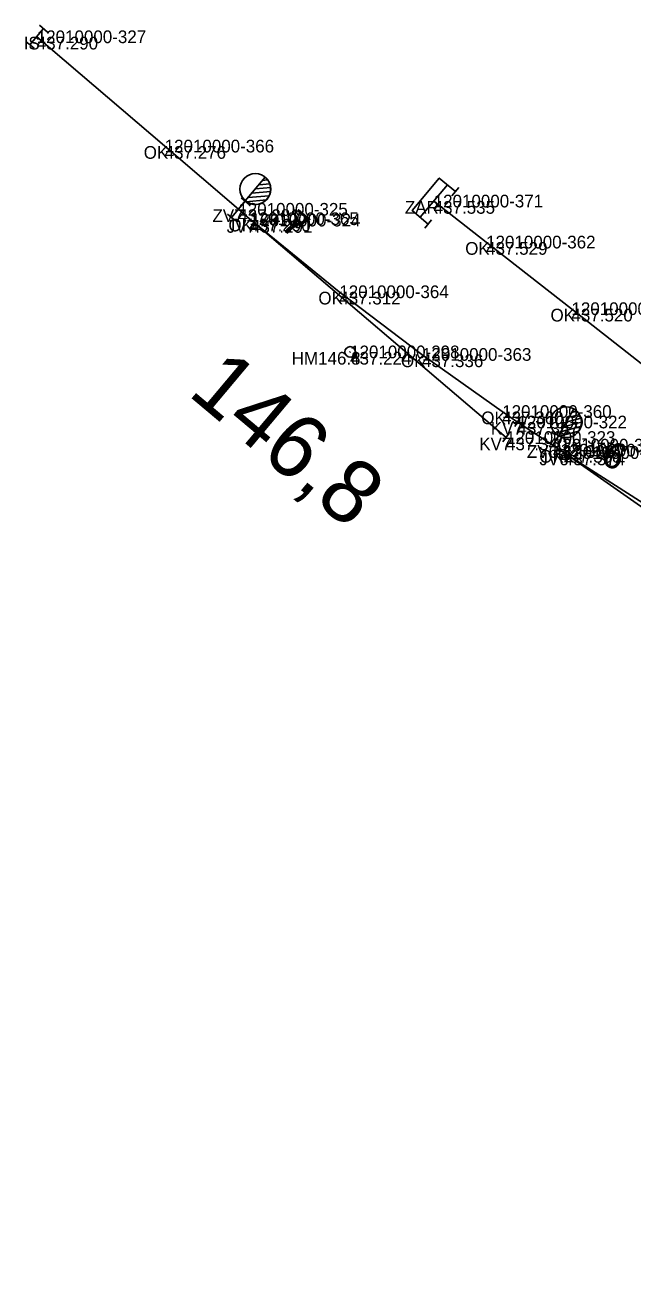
# Model space of a CAD drawing. Extents: x -653665 to -652742, y -1166300 to -1165487.
# Drawn here: x -653457.5 to -653400, y -1165780.3 to -1165660.7 of the extents above; entities that cross this region are included whole.
import ezdxf

# ---------------------------------------------------------------- set-up
doc = ezdxf.new("R2010")
doc.units = 0
for name, color, linetype in [('Vrstva 1', 7, 'Continuous'), ('Vrstva 15', 7, 'Continuous'), ('Vrstva 2', 7, 'Continuous'), ('Vrstva 3', 7, 'Continuous'), ('Vrstva 60', 7, 'Continuous'), ('Vrstva 61', 7, 'Continuous'), ('Vrstva 62', 7, 'Continuous'), ('Vrstva 7', 7, 'Continuous')]:
    doc.layers.add(name, color=color, linetype=linetype)

msp = doc.modelspace()

# ---------------------------------------------------------------- linework, layer by layer
at = {"layer": 'Vrstva 1'}
for points in [[(-653437.34, -1165678.06), (-653444.31, -1165672.07), (-653456.41, -1165661.74)], [(-653407.58, -1165700.37), (-653410.93, -1165698.18), (-653412.38, -1165697.19), (-653419.97, -1165691.79), (-653427.79, -1165685.86), (-653436.14, -1165679.08), (-653436.3, -1165678.95), (-653437.34, -1165678.06)], [(-653412.02, -1165699.65), (-653436.14, -1165679.08), (-653436.3, -1165678.95), (-653437.34, -1165678.06)], [(-653322.72, -1165752.72), (-653325.73, -1165750.35), (-653329.43, -1165747.45), (-653337.98, -1165740.73), (-653346.02, -1165734.53), (-653350.36, -1165731.09), (-653358.44, -1165724.74), (-653366.11, -1165718.7), (-653373.96, -1165712.53), (-653382.2, -1165706.04), (-653390.04, -1165699.88), (-653398.07, -1165693.55), (-653405.83, -1165687.47), (-653413.9, -1165681.16), (-653418.86, -1165677.28)], [(-653303.11, -1165780.26), (-653310.99, -1165774.05), (-653319.17, -1165767.61), (-653327.03, -1165761.43), (-653331.89, -1165757.62), (-653335.5, -1165754.8), (-653344.08, -1165748.08), (-653352.04, -1165741.96), (-653356.22, -1165738.72), (-653363.93, -1165732.78), (-653371.45, -1165727), (-653371.62, -1165726.86), (-653379.2, -1165721.04), (-653387.07, -1165715.03), (-653387.21, -1165714.92), (-653393.27, -1165710.42), (-653395.2, -1165709.02), (-653406.55, -1165701.06), (-653406.89, -1165700.83), (-653407.58, -1165700.37)], [(-653381.84, -1165716.08), (-653384.56, -1165714.53), (-653386.13, -1165713.64), (-653386.38, -1165713.51), (-653392.82, -1165709.75), (-653395.64, -1165708.03), (-653406.55, -1165701.06), (-653406.89, -1165700.83), (-653407.58, -1165700.37)]]:
    msp.add_lwpolyline(points, dxfattribs=at)
at = {"layer": 'Vrstva 15'}
for p, q in [((-653420.15, -1165678.81), (-653417.57, -1165675.75)), ((-653417.13, -1165676.78), (-653416.49, -1165676.01)), ((-653419.7, -1165679.84), (-653419.06, -1165679.07))]:
    msp.add_line(p, q, dxfattribs=at)
msp.add_lwpolyline([(-653416.81, -1165676.39), (-653418.34, -1165675.11), (-653420.91, -1165678.17), (-653419.38, -1165679.46)], dxfattribs=at)
at = {"layer": 'Vrstva 2'}
for p, q in [((-653436.68, -1165677.27), (-653434.8, -1165675.03)), ((-653435.38, -1165675.73), (-653434.37, -1165675.64)), ((-653435.04, -1165675.32), (-653434.57, -1165675.28)), ((-653436.4, -1165676.95), (-653434.41, -1165676.77)), ((-653436.06, -1165676.54), (-653434.29, -1165676.38)), ((-653435.72, -1165676.13), (-653434.28, -1165676.01)), ((-653436.68, -1165677.27), (-653437.34, -1165678.06)), ((-653436.68, -1165677.27), (-653436.68, -1165677.27)), ((-653436.59, -1165677.34), (-653434.69, -1165677.17)), ((-653407.07, -1165699.48), (-653405.61, -1165696.94)), ((-653406.06, -1165697.73), (-653405.08, -1165697.47)), ((-653405.8, -1165697.27), (-653405.34, -1165697.15)), ((-653410.68, -1165697.74), (-653411.18, -1165698.61)), ((-653406.86, -1165699.11), (-653404.93, -1165698.59)), ((-653406.6, -1165698.65), (-653404.88, -1165698.19)), ((-653406.33, -1165698.19), (-653404.93, -1165697.82)), ((-653411.73, -1165699.24), (-653412.31, -1165700.06)), ((-653407.07, -1165699.48), (-653407.58, -1165700.37)), ((-653407.07, -1165699.48), (-653407.07, -1165699.48)), ((-653406.97, -1165699.53), (-653405.14, -1165699.04))]:
    msp.add_line(p, q, dxfattribs=at)
for centre in [(-653435.73, -1165676.14), (-653406.34, -1165698.2)]:
    msp.add_circle(centre, 1.46, dxfattribs=at)
for centre, start, end in [((-653435.74, -1165676.15), 230.0196, 49.9804), ((-653406.34, -1165698.21), 240.0196, 59.9804)]:
    msp.add_arc(centre, 1.46, start, end, dxfattribs=at)
at = {"layer": 'Vrstva 3'}
for p, q in [((-653455.77, -1165660.97), (-653457.06, -1165662.51)), ((-653456.15, -1165660.65), (-653455.39, -1165661.3)), ((-653457.44, -1165662.18), (-653456.67, -1165662.83)), ((-653437.08, -1165676.97), (-653436.31, -1165677.62)), ((-653436.69, -1165677.29), (-653437.98, -1165678.83)), ((-653438.36, -1165678.51), (-653437.6, -1165679.15))]:
    msp.add_line(p, q, dxfattribs=at)
at = {"layer": 'Vrstva 60'}
for p, q in [((-653456.41, -1165661.74), (-653456.41, -1165661.74)), ((-653444.31, -1165672.07), (-653444.31, -1165672.07)), ((-653437.34, -1165678.06), (-653437.34, -1165678.06)), ((-653418.86, -1165677.28), (-653418.86, -1165677.28)), ((-653436.3, -1165678.95), (-653436.3, -1165678.95)), ((-653436.14, -1165679.08), (-653436.14, -1165679.08)), ((-653413.9, -1165681.16), (-653413.9, -1165681.16)), ((-653427.79, -1165685.86), (-653427.79, -1165685.86)), ((-653405.83, -1165687.47), (-653405.83, -1165687.47)), ((-653426.77, -1165691.55), (-653426.77, -1165691.55)), ((-653419.97, -1165691.79), (-653419.97, -1165691.79)), ((-653412.38, -1165697.19), (-653412.38, -1165697.19)), ((-653410.93, -1165698.18), (-653410.93, -1165698.18)), ((-653412.02, -1165699.65), (-653412.02, -1165699.65)), ((-653407.58, -1165700.37), (-653407.58, -1165700.37)), ((-653406.89, -1165700.83), (-653406.89, -1165700.83)), ((-653406.55, -1165701.06), (-653406.55, -1165701.06))]:
    msp.add_line(p, q, dxfattribs=at)
at = {"layer": 'Vrstva 7'}
msp.add_line((-653426.81, -1165691.52), (-653426.74, -1165691.59), dxfattribs=at)
msp.add_circle((-653426.77, -1165691.55), 0.5, dxfattribs=at)

# ---------------------------------------------------------------- texts
at = {"layer": 'Vrstva 2'}
for s, rotation, p in [('7', 320, (-653433.38, -1165679.82)), ('6', 330, (-653403.16, -1165701.97))]:
    msp.add_text(s, height=2.5, rotation=rotation, dxfattribs=at).set_placement(p)
at = {"layer": 'Vrstva 60'}
for s, p in [('12010000-327', (-653456.41, -1165662.34)), ('12010000-366', (-653444.31, -1165672.68)), ('12010000-371', (-653418.86, -1165677.88)), ('12010000-325', (-653437.34, -1165678.66)), ('12010000-365', (-653436.3, -1165679.55)), ('12010000-324', (-653436.14, -1165679.68)), ('12010000-362', (-653413.9, -1165681.76)), ('12010000-364', (-653427.79, -1165686.46)), ('12010000-361', (-653405.83, -1165688.06)), ('12010000-298', (-653426.77, -1165692.15)), ('12010000-363', (-653419.97, -1165692.39)), ('12010000-360', (-653412.38, -1165697.79)), ('12010000-322', (-653410.93, -1165698.78)), ('12010000-323', (-653412.02, -1165700.25)), ('12010000-321', (-653407.58, -1165700.97)), ('12010000-359', (-653406.89, -1165701.44)), ('12010000-320', (-653406.55, -1165701.67))]:
    msp.add_text(s, height=1.2, dxfattribs=at).set_placement(p)
at = {"layer": 'Vrstva 61'}
for s, p in [('437.290', (-653456.41, -1165662.94)), ('437.276', (-653444.31, -1165673.28)), ('437.281', (-653437.34, -1165679.26)), ('437.535', (-653418.86, -1165678.48)), ('437.290', (-653436.3, -1165680.15)), ('437.291', (-653436.14, -1165680.28)), ('437.529', (-653413.9, -1165682.36)), ('437.312', (-653427.79, -1165687.06)), ('437.520', (-653405.83, -1165688.67)), ('437.224', (-653426.77, -1165692.75)), ('437.336', (-653419.97, -1165692.99)), ('437.360', (-653412.38, -1165698.39)), ('437.357', (-653410.93, -1165699.38)), ('437.340', (-653412.02, -1165700.85)), ('437.366', (-653407.58, -1165701.57)), ('437.368', (-653406.89, -1165702.03)), ('437.374', (-653406.55, -1165702.27))]:
    msp.add_text(s, height=1.2, dxfattribs=at).set_placement(p)
at = {"layer": 'Vrstva 62'}
for s, p in [('IS', (-653457.64, -1165662.94)), ('OK', (-653446.29, -1165673.28)), ('ZV7', (-653439.79, -1165679.26)), ('ZAR', (-653421.59, -1165678.48)), ('JV7', (-653438.44, -1165680.28)), ('OK', (-653438.28, -1165680.15)), ('OK', (-653415.88, -1165682.36)), ('OK', (-653429.77, -1165687.06)), ('OK', (-653407.81, -1165688.67)), ('HM146.8', (-653432.29, -1165692.75)), ('OK', (-653421.96, -1165692.99)), ('OK', (-653414.36, -1165698.39)), ('KV7', (-653413.46, -1165699.38)), ('KV7', (-653414.55, -1165700.85)), ('ZV6', (-653410.04, -1165701.57)), ('JV6', (-653408.86, -1165702.27)), ('OK', (-653408.87, -1165702.03))]:
    msp.add_text(s, height=1.2, dxfattribs=at).set_placement(p)
at = {"layer": 'Vrstva 7'}
msp.add_text('146,8', height=6, rotation=320, dxfattribs=at).set_placement((-653442.23, -1165695.55))

doc.saveas('drawing.dxf')
